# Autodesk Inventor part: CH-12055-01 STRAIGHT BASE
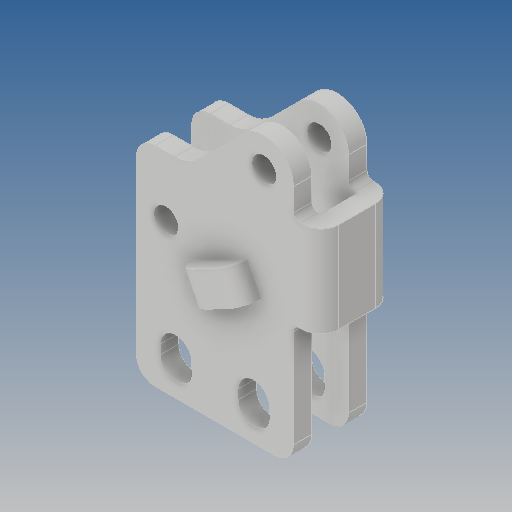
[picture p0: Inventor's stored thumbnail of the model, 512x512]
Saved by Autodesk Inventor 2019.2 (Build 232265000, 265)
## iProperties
Created: 2015-08
Part Number: CH-12055-01 STRAIGHT BASE
Material: Ogólny
Document SubType Name: Modeling
Designer: CADENGINEERING4
Density: 1 g/cm^3
Appearance: Domyślna
Author: CADENGINEERING4
Revision Number: ÈÎºÎ
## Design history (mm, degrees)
feature "Ô²½Ç2"
node "Bryła1"
